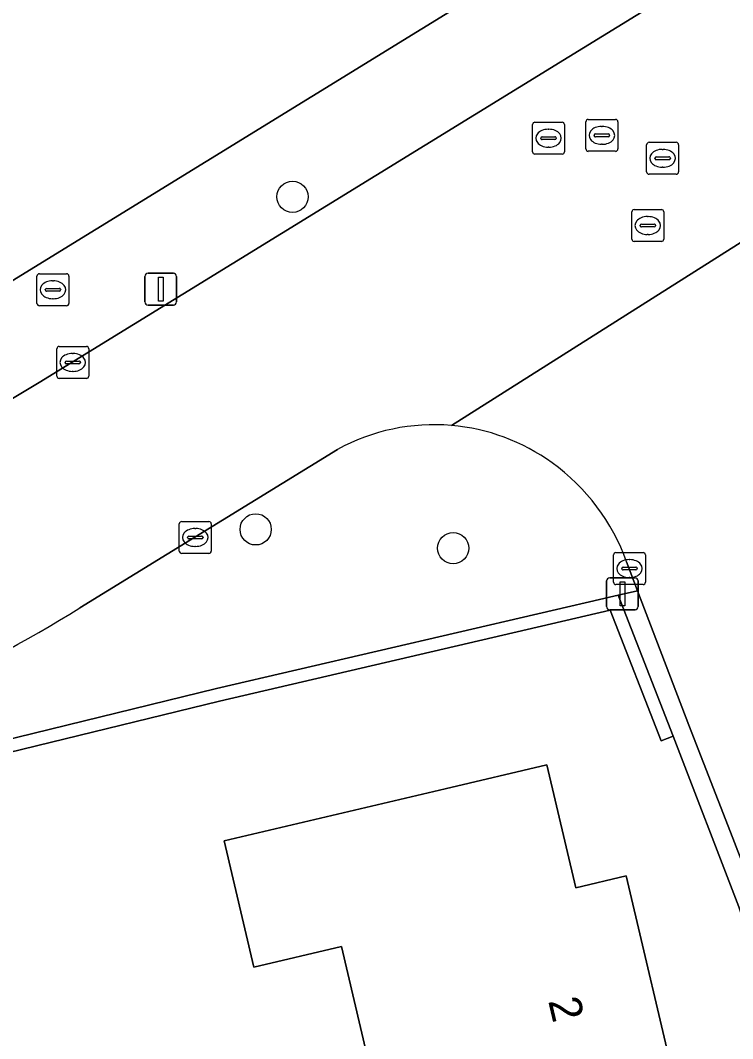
# Model space of a CAD drawing. Extents: x 157648 to 158502, y 379212 to 380938.
# Drawn here: x 158245.9 to 158268.23, y 380643.22 to 380675.11 of the extents above; entities that cross this region are included whole.
import ezdxf

# ---------------------------------------------------------------- set-up
doc = ezdxf.new("R2010")
doc.units = 0
for name, color, linetype in [('IMGEO_Boom', 7, 'Continuous'), ('IMGEO_Brandkraan', 7, 'Continuous'), ('IMGEO_Erf', 7, 'Continuous'), ('IMGEO_Groenvoorziening', 7, 'Continuous'), ('IMGEO_Haag', 7, 'Continuous'), ('IMGEO_Kolk', 7, 'Continuous'), ('IMGEO_Lichtmast', 7, 'Continuous'), ('IMGEO_Pand', 7, 'Continuous'), ('IMGEO_Pand_nummerreeks', 7, 'Continuous'), ('IMGEO_Rijbaan_lokaal_open', 7, 'Continuous'), ('IMGEO_Rioolput', 7, 'Continuous'), ('IMGEO_Voetpad_open', 7, 'Continuous')]:
    doc.layers.add(name, color=color, linetype=linetype)

msp = doc.modelspace()

# ---------------------------------------------------------------- linework, layer by layer
at = {"layer": 'IMGEO_Boom'}
for centre in [(158254.434, 380669.59), (158253.28, 380659.173), (158259.468, 380658.585)]:
    msp.add_circle(centre, 0.489, dxfattribs=at)
at = {"layer": 'IMGEO_Brandkraan'}
for p, q in [((158246.425, 380666.251), (158246.425, 380667.103)), ((158246.5, 380667.177), (158247.352, 380667.177)), ((158246.913, 380666.957), (158246.938, 380666.957)), ((158247.426, 380667.103), (158247.426, 380666.251)), ((158246.684, 380666.671), (158246.684, 380666.683)), ((158247.122, 380666.634), (158246.724, 380666.634)), ((158246.727, 380666.72), (158247.125, 380666.72)), ((158247.168, 380666.683), (158247.168, 380666.671)), ((158246.936, 380666.397), (158246.911, 380666.397)), ((158247.352, 380666.177), (158246.5, 380666.177))]:
    msp.add_line(p, q, dxfattribs=at)
for points in [[(158246.425, 380666.251), (158246.425, 380667.103)], [(158246.5, 380667.177), (158247.352, 380667.177)], [(158247.426, 380667.103), (158247.426, 380666.251)], [(158247.352, 380666.177), (158246.5, 380666.177)]]:
    msp.add_lwpolyline(points, dxfattribs=at)
for centre, radius, start, end in [((158246.502, 380667.101), 0.0765, 91.552, 178.448), ((158246.502, 380667.101), 0.0765, 91.552, 178.448), ((158247.35, 380667.101), 0.0765, 1.552, 88.448), ((158247.35, 380667.101), 0.0765, 1.552, 88.448), ((158246.724, 380666.68), 0.0403, 85.8775, 175.7526), ((158246.721, 380666.67), 0.0366, 178.938, 274.7102), ((158247.125, 380666.677), 0.043, 264.8664, 352.4533), ((158247.129, 380666.682), 0.0386, 1.7309, 96.639), ((158246.502, 380666.253), 0.0765, 181.552, 268.448), ((158246.502, 380666.253), 0.0765, 181.552, 268.448), ((158247.35, 380666.253), 0.0765, 271.552, 358.448), ((158247.35, 380666.253), 0.0765, 271.552, 358.448)]:
    msp.add_arc(centre, radius, start, end, dxfattribs=at)
for centre, major_axis, ratio, start_param, end_param in [((158246.912, 380666.677), (-0.387, 0.002), 0.722429, 4.712389, 7.853982), ((158246.937, 380666.677), (-0.39, 0.002), 0.717154, 1.570796, 4.712389)]:
    msp.add_ellipse(centre, major_axis=major_axis, ratio=ratio, start_param=start_param, end_param=end_param, dxfattribs=at)
at = {"layer": 'IMGEO_Erf'}
for points in [[(158244.961, 380666.536), (158268.56, 380681.046), (158278.546, 380687.175), (158281.278, 380688.781)], [(158270.472, 380641.386), (158268.423, 380647.352), (158266.359, 380652.693), (158265.986, 380652.548), (158264.393, 380656.642), (158252.147, 380653.798), (158240.661, 380650.992), (158240.566, 380651.381), (158230.925, 380649.086), (158227.242, 380648.21), (158204.018, 380642.406)], [(158257.561, 380639.351), (158255.967, 380646.114), (158253.226, 380645.468), (158252.295, 380649.421), (158259.217, 380651.052), (158262.407, 380651.804), (158263.315, 380647.952), (158264.89, 380648.323), (158266.508, 380641.458)]]:
    msp.add_lwpolyline(points, dxfattribs=at)
at = {"layer": 'IMGEO_Groenvoorziening'}
msp.add_lwpolyline([(158265.986, 380652.548), (158266.359, 380652.693), (158264.64, 380657.11), (158252.054, 380654.187), (158240.566, 380651.381), (158240.661, 380650.992), (158252.147, 380653.798), (158264.393, 380656.642)], close=True, dxfattribs=at)
at = {"layer": 'IMGEO_Haag'}
msp.add_lwpolyline([(158265.986, 380652.548), (158266.359, 380652.693), (158264.64, 380657.11), (158252.054, 380654.187), (158240.566, 380651.381), (158240.661, 380650.992), (158252.147, 380653.798), (158264.393, 380656.642)], close=True, dxfattribs=at)
at = {"layer": 'IMGEO_Kolk'}
for p, q in [((158247.046, 380663.975), (158247.046, 380664.827)), ((158247.121, 380664.901), (158247.973, 380664.901)), ((158247.534, 380664.681), (158247.559, 380664.681)), ((158248.047, 380664.827), (158248.047, 380663.975)), ((158247.305, 380664.395), (158247.305, 380664.407)), ((158247.743, 380664.358), (158247.345, 380664.358)), ((158247.348, 380664.444), (158247.746, 380664.444)), ((158247.789, 380664.407), (158247.789, 380664.395)), ((158247.557, 380664.121), (158247.532, 380664.121)), ((158247.973, 380663.901), (158247.121, 380663.901)), ((158250.886, 380658.494), (158250.886, 380659.346)), ((158250.961, 380659.42), (158251.813, 380659.42)), ((158251.887, 380659.346), (158251.887, 380658.494)), ((158251.145, 380658.914), (158251.145, 380658.926)), ((158251.188, 380658.963), (158251.586, 380658.963)), ((158251.374, 380659.2), (158251.399, 380659.2)), ((158251.629, 380658.926), (158251.629, 380658.914)), ((158251.583, 380658.877), (158251.185, 380658.877)), ((158251.397, 380658.64), (158251.372, 380658.64)), ((158251.813, 380658.42), (158250.961, 380658.42)), ((158264.493, 380657.52), (158264.493, 380658.372)), ((158264.568, 380658.446), (158265.42, 380658.446)), ((158265.494, 380658.372), (158265.494, 380657.52)), ((158264.752, 380657.94), (158264.752, 380657.952)), ((158264.795, 380657.989), (158265.193, 380657.989)), ((158264.981, 380658.226), (158265.006, 380658.226)), ((158265.236, 380657.952), (158265.236, 380657.94)), ((158265.19, 380657.903), (158264.792, 380657.903)), ((158265.004, 380657.666), (158264.979, 380657.666)), ((158265.42, 380657.446), (158264.568, 380657.446))]:
    msp.add_line(p, q, dxfattribs=at)
for points in [[(158247.046, 380663.975), (158247.046, 380664.827)], [(158247.121, 380664.901), (158247.973, 380664.901)], [(158248.047, 380664.827), (158248.047, 380663.975)], [(158247.973, 380663.901), (158247.121, 380663.901)], [(158250.886, 380658.494), (158250.886, 380659.346)], [(158250.961, 380659.42), (158251.813, 380659.42)], [(158251.887, 380659.346), (158251.887, 380658.494)], [(158251.813, 380658.42), (158250.961, 380658.42)], [(158264.493, 380657.52), (158264.493, 380658.372)], [(158264.568, 380658.446), (158265.42, 380658.446)], [(158265.494, 380658.372), (158265.494, 380657.52)], [(158265.42, 380657.446), (158264.568, 380657.446)]]:
    msp.add_lwpolyline(points, dxfattribs=at)
for centre, radius, start, end in [((158247.123, 380664.825), 0.0765, 91.552, 178.448), ((158247.123, 380664.825), 0.0765, 91.552, 178.448), ((158247.971, 380664.825), 0.0765, 1.552, 88.448), ((158247.971, 380664.825), 0.0765, 1.552, 88.448), ((158247.345, 380664.404), 0.0403, 85.8775, 175.7526), ((158247.342, 380664.394), 0.0366, 178.938, 274.7102), ((158247.746, 380664.401), 0.043, 264.8664, 352.4533), ((158247.75, 380664.406), 0.0386, 1.7309, 96.639), ((158247.123, 380663.977), 0.0765, 181.552, 268.448), ((158247.123, 380663.977), 0.0765, 181.552, 268.448), ((158247.971, 380663.977), 0.0765, 271.552, 358.448), ((158247.971, 380663.977), 0.0765, 271.552, 358.448), ((158250.963, 380659.344), 0.0765, 91.552, 178.448), ((158250.963, 380659.344), 0.0765, 91.552, 178.448), ((158251.811, 380659.344), 0.0765, 1.552, 88.448), ((158251.811, 380659.344), 0.0765, 1.552, 88.448), ((158251.185, 380658.923), 0.0403, 85.8775, 175.7526), ((158251.182, 380658.913), 0.0366, 178.938, 274.7102), ((158251.586, 380658.92), 0.043, 264.8664, 352.4533), ((158251.59, 380658.925), 0.0386, 1.7309, 96.639), ((158250.963, 380658.496), 0.0765, 181.552, 268.448), ((158250.963, 380658.496), 0.0765, 181.552, 268.448), ((158251.811, 380658.496), 0.0765, 271.552, 358.448), ((158251.811, 380658.496), 0.0765, 271.552, 358.448), ((158264.57, 380658.37), 0.0765, 91.552, 178.448), ((158264.57, 380658.37), 0.0765, 91.552, 178.448), ((158265.418, 380658.37), 0.0765, 1.552, 88.448), ((158265.418, 380658.37), 0.0765, 1.552, 88.448), ((158264.792, 380657.949), 0.0403, 85.8775, 175.7526), ((158265.197, 380657.951), 0.0386, 1.7309, 96.639), ((158264.789, 380657.939), 0.0366, 178.938, 274.7102), ((158265.193, 380657.946), 0.043, 264.8664, 352.4533), ((158264.57, 380657.522), 0.0765, 181.552, 268.448), ((158264.57, 380657.522), 0.0765, 181.552, 268.448), ((158265.418, 380657.522), 0.0765, 271.552, 358.448), ((158265.418, 380657.522), 0.0765, 271.552, 358.448)]:
    msp.add_arc(centre, radius, start, end, dxfattribs=at)
for centre, major_axis, ratio, start_param, end_param in [((158247.533, 380664.401), (-0.387, 0.002), 0.722429, 4.712389, 7.853982), ((158247.558, 380664.401), (-0.39, 0.002), 0.717154, 1.570796, 4.712389), ((158251.373, 380658.92), (-0.387, 0.002), 0.722429, 4.712389, 7.853982), ((158251.398, 380658.92), (-0.39, 0.002), 0.717154, 1.570796, 4.712389), ((158264.98, 380657.946), (-0.387, 0.002), 0.722429, 4.712389, 7.853982), ((158265.005, 380657.946), (-0.39, 0.002), 0.717154, 1.570796, 4.712389)]:
    msp.add_ellipse(centre, major_axis=major_axis, ratio=ratio, start_param=start_param, end_param=end_param, dxfattribs=at)
at = {"layer": 'IMGEO_Lichtmast'}
for p, q in [((158249.81, 380666.295), (158249.81, 380667.095)), ((158249.81, 380667.095), (158249.81, 380666.295)), ((158249.91, 380667.195), (158250.7, 380667.195)), ((158250.7, 380667.195), (158249.91, 380667.195)), ((158250.8, 380667.095), (158250.8, 380666.295)), ((158250.8, 380666.295), (158250.8, 380667.095)), ((158250.7, 380666.195), (158249.91, 380666.195)), ((158249.91, 380666.195), (158250.7, 380666.195)), ((158264.378, 380657.657), (158265.168, 380657.657)), ((158265.168, 380657.657), (158264.378, 380657.657)), ((158264.278, 380656.757), (158264.278, 380657.557)), ((158264.278, 380657.557), (158264.278, 380656.757)), ((158265.268, 380657.557), (158265.268, 380656.757)), ((158265.268, 380656.757), (158265.268, 380657.557)), ((158265.168, 380656.657), (158264.378, 380656.657)), ((158264.378, 380656.657), (158265.168, 380656.657))]:
    msp.add_line(p, q, dxfattribs=at)
for points in [[(158250.23, 380667.07), (158250.38, 380667.07), (158250.38, 380666.32), (158250.23, 380666.32), (158250.23, 380667.07)], [(158264.698, 380657.532), (158264.848, 380657.532), (158264.848, 380656.782), (158264.698, 380656.782), (158264.698, 380657.532)]]:
    msp.add_lwpolyline(points, dxfattribs=at)
for centre, start, end in [((158249.91, 380667.095), 90, 180), ((158249.91, 380667.095), 90, 180), ((158250.7, 380667.095), 0, 90), ((158250.7, 380667.095), 360, 90), ((158249.91, 380666.295), 180, 270), ((158249.91, 380666.295), 180, 270), ((158250.7, 380666.295), 270, 0), ((158250.7, 380666.295), 270, 0), ((158264.378, 380657.557), 90, 180), ((158264.378, 380657.557), 90, 180), ((158265.168, 380657.557), 0, 90), ((158265.168, 380657.557), 360, 90), ((158264.378, 380656.757), 180, 270), ((158264.378, 380656.757), 180, 270), ((158265.168, 380656.757), 270, 0), ((158265.168, 380656.757), 270, 0)]:
    msp.add_arc(centre, 0.1, start, end, dxfattribs=at)
at = {"layer": 'IMGEO_Pand'}
msp.add_lwpolyline([(158262.407, 380651.804), (158259.217, 380651.052), (158252.295, 380649.421), (158253.226, 380645.468), (158255.967, 380646.114), (158257.561, 380639.351), (158266.508, 380641.458), (158264.89, 380648.323), (158263.315, 380647.952)], close=True, dxfattribs=at)
at = {"layer": 'IMGEO_Rijbaan_lokaal_open'}
for points in [[(158280.194, 380684.478), (158268.424, 380677.249), (158268.233, 380677.131), (158263.098, 380673.967), (158246.494, 380663.768), (158243.889, 380662.222), (158239.92, 380659.948)], [(158269.209, 380668.62), (158259.413, 380662.428)], [(158259.413, 380662.428), (158269.209, 380668.62)], [(158247.773, 380656.714), (158255.847, 380661.679)], [(158264.905, 380658.157), (158265.25, 380657.252), (158266.856, 380653.04), (158268.233, 380649.501), (158268.951, 380647.635), (158271.067, 380641.515), (158273.069, 380635.27), (158274.89, 380628.688), (158275.399, 380626.75), (158277.479, 380617.972), (158278.213, 380614.328)]]:
    msp.add_lwpolyline(points, dxfattribs=at)
for centre, radius, start, end in [((158258.874, 380656.129), 6.322, 85.1134, 118.6105), ((158258.879, 380656.149), 6.302, 54.1519, 85.1345), ((158258.703, 380655.913), 6.596, 19.8874, 54.1122), ((158215.577, 380709.566), 61.886, 290.21525, 301.3483)]:
    msp.add_arc(centre, radius, start, end, dxfattribs=at)
at = {"layer": 'IMGEO_Rioolput'}
for p, q in [((158263.704, 380672.012), (158264.556, 380672.012)), ((158261.956, 380670.997), (158261.956, 380671.849)), ((158262.031, 380671.923), (158262.883, 380671.923)), ((158262.444, 380671.703), (158262.469, 380671.703)), ((158262.957, 380671.849), (158262.957, 380670.997)), ((158263.629, 380671.086), (158263.629, 380671.938)), ((158264.117, 380671.792), (158264.142, 380671.792)), ((158264.63, 380671.938), (158264.63, 380671.086)), ((158262.215, 380671.417), (158262.215, 380671.429)), ((158262.653, 380671.38), (158262.255, 380671.38)), ((158262.258, 380671.466), (158262.656, 380671.466)), ((158262.699, 380671.429), (158262.699, 380671.417)), ((158263.888, 380671.506), (158263.888, 380671.518)), ((158264.326, 380671.469), (158263.928, 380671.469)), ((158263.931, 380671.555), (158264.329, 380671.555)), ((158264.372, 380671.518), (158264.372, 380671.506)), ((158262.467, 380671.143), (158262.442, 380671.143)), ((158264.14, 380671.232), (158264.115, 380671.232)), ((158265.532, 380670.368), (158265.532, 380671.22)), ((158265.607, 380671.294), (158266.459, 380671.294)), ((158266.02, 380671.074), (158266.045, 380671.074)), ((158266.533, 380671.22), (158266.533, 380670.368)), ((158262.883, 380670.923), (158262.031, 380670.923)), ((158264.556, 380671.012), (158263.704, 380671.012)), ((158265.791, 380670.788), (158265.791, 380670.8)), ((158266.229, 380670.751), (158265.831, 380670.751)), ((158265.834, 380670.837), (158266.232, 380670.837)), ((158266.275, 380670.8), (158266.275, 380670.788)), ((158266.043, 380670.514), (158266.018, 380670.514)), ((158266.459, 380670.294), (158265.607, 380670.294)), ((158265.067, 380668.263), (158265.067, 380669.115)), ((158265.142, 380669.189), (158265.994, 380669.189)), ((158266.068, 380669.115), (158266.068, 380668.263)), ((158265.555, 380668.969), (158265.58, 380668.969)), ((158265.326, 380668.683), (158265.326, 380668.695)), ((158265.764, 380668.646), (158265.366, 380668.646)), ((158265.369, 380668.732), (158265.767, 380668.732)), ((158265.81, 380668.695), (158265.81, 380668.683)), ((158265.994, 380668.189), (158265.142, 380668.189)), ((158265.578, 380668.409), (158265.553, 380668.409))]:
    msp.add_line(p, q, dxfattribs=at)
for points in [[(158263.704, 380672.012), (158264.556, 380672.012)], [(158261.956, 380670.997), (158261.956, 380671.849)], [(158262.031, 380671.923), (158262.883, 380671.923)], [(158262.957, 380671.849), (158262.957, 380670.997)], [(158263.629, 380671.086), (158263.629, 380671.938)], [(158264.63, 380671.938), (158264.63, 380671.086)], [(158265.532, 380670.368), (158265.532, 380671.22)], [(158265.607, 380671.294), (158266.459, 380671.294)], [(158266.533, 380671.22), (158266.533, 380670.368)], [(158262.883, 380670.923), (158262.031, 380670.923)], [(158264.556, 380671.012), (158263.704, 380671.012)], [(158266.459, 380670.294), (158265.607, 380670.294)], [(158265.067, 380668.263), (158265.067, 380669.115)], [(158265.142, 380669.189), (158265.994, 380669.189)], [(158266.068, 380669.115), (158266.068, 380668.263)], [(158265.994, 380668.189), (158265.142, 380668.189)]]:
    msp.add_lwpolyline(points, dxfattribs=at)
for centre, radius, start, end in [((158263.706, 380671.936), 0.0765, 91.552, 178.448), ((158263.706, 380671.936), 0.0765, 91.552, 178.448), ((158264.554, 380671.936), 0.0765, 1.552, 88.448), ((158264.554, 380671.936), 0.0765, 1.552, 88.448), ((158262.033, 380671.847), 0.0765, 91.552, 178.448), ((158262.033, 380671.847), 0.0765, 91.552, 178.448), ((158262.881, 380671.847), 0.0765, 1.552, 88.448), ((158262.881, 380671.847), 0.0765, 1.552, 88.448), ((158262.255, 380671.426), 0.0403, 85.8775, 175.7526), ((158262.252, 380671.416), 0.0366, 178.938, 274.7102), ((158262.656, 380671.423), 0.043, 264.8664, 352.4533), ((158262.66, 380671.428), 0.0386, 1.7309, 96.639), ((158263.928, 380671.515), 0.0403, 85.8775, 175.7526), ((158263.925, 380671.505), 0.0366, 178.938, 274.7102), ((158264.329, 380671.512), 0.043, 264.8664, 352.4533), ((158264.333, 380671.517), 0.0386, 1.7309, 96.639), ((158263.706, 380671.088), 0.0765, 181.552, 268.448), ((158263.706, 380671.088), 0.0765, 181.552, 268.448), ((158264.554, 380671.088), 0.0765, 271.552, 358.448), ((158264.554, 380671.088), 0.0765, 271.552, 358.448), ((158265.609, 380671.218), 0.0765, 91.552, 178.448), ((158265.609, 380671.218), 0.0765, 91.552, 178.448), ((158266.457, 380671.218), 0.0765, 1.552, 88.448), ((158266.457, 380671.218), 0.0765, 1.552, 88.448), ((158262.033, 380670.999), 0.0765, 181.552, 268.448), ((158262.033, 380670.999), 0.0765, 181.552, 268.448), ((158262.881, 380670.999), 0.0765, 271.552, 358.448), ((158262.881, 380670.999), 0.0765, 271.552, 358.448), ((158265.831, 380670.797), 0.0403, 85.8775, 175.7526), ((158265.828, 380670.787), 0.0366, 178.938, 274.7102), ((158266.232, 380670.794), 0.043, 264.8664, 352.4533), ((158266.236, 380670.799), 0.0386, 1.7309, 96.639), ((158265.609, 380670.37), 0.0765, 181.552, 268.448), ((158265.609, 380670.37), 0.0765, 181.552, 268.448), ((158266.457, 380670.37), 0.0765, 271.552, 358.448), ((158266.457, 380670.37), 0.0765, 271.552, 358.448), ((158265.144, 380669.113), 0.0765, 91.552, 178.448), ((158265.144, 380669.113), 0.0765, 91.552, 178.448), ((158265.992, 380669.113), 0.0765, 1.552, 88.448), ((158265.992, 380669.113), 0.0765, 1.552, 88.448), ((158265.366, 380668.692), 0.0403, 85.8775, 175.7526), ((158265.363, 380668.682), 0.0366, 178.938, 274.7102), ((158265.767, 380668.689), 0.043, 264.8664, 352.4533), ((158265.771, 380668.694), 0.0386, 1.7309, 96.639), ((158265.144, 380668.265), 0.0765, 181.552, 268.448), ((158265.144, 380668.265), 0.0765, 181.552, 268.448), ((158265.992, 380668.265), 0.0765, 271.552, 358.448), ((158265.992, 380668.265), 0.0765, 271.552, 358.448)]:
    msp.add_arc(centre, radius, start, end, dxfattribs=at)
for centre, major_axis, ratio, start_param, end_param in [((158262.443, 380671.423), (-0.387, 0.002), 0.722429, 4.712389, 7.853982), ((158262.468, 380671.423), (-0.39, 0.002), 0.717154, 1.570796, 4.712389), ((158264.116, 380671.512), (-0.387, 0.002), 0.722429, 4.712389, 7.853982), ((158264.141, 380671.512), (-0.39, 0.002), 0.717154, 1.570796, 4.712389), ((158266.019, 380670.794), (-0.387, 0.002), 0.722429, 4.712389, 7.853982), ((158266.044, 380670.794), (-0.39, 0.002), 0.717154, 1.570796, 4.712389), ((158265.554, 380668.689), (-0.387, 0.002), 0.722429, 4.712389, 7.853982), ((158265.579, 380668.689), (-0.39, 0.002), 0.717154, 1.570796, 4.712389)]:
    msp.add_ellipse(centre, major_axis=major_axis, ratio=ratio, start_param=start_param, end_param=end_param, dxfattribs=at)
at = {"layer": 'IMGEO_Voetpad_open'}
for points in [[(158281.278, 380688.781), (158278.546, 380687.175), (158268.56, 380681.046), (158244.961, 380666.536), (158241.255, 380664.317)], [(158239.92, 380659.948), (158243.889, 380662.222), (158246.494, 380663.768), (158263.098, 380673.967), (158268.233, 380677.131), (158268.424, 380677.249), (158280.194, 380684.478)], [(158255.847, 380661.679), (158247.773, 380656.714)], [(158264.64, 380657.11), (158265.25, 380657.252), (158264.905, 380658.157)], [(158231.021, 380649.606), (158230.806, 380649.557), (158227.136, 380648.639), (158217.494, 380646.285), (158213.812, 380645.387), (158203.627, 380642.926), (158199.947, 380642.048), (158190.411, 380639.762), (158186.738, 380638.899), (158176.96, 380636.568), (158177.087, 380635.99), (158179.163, 380636.483), (158184.083, 380637.656), (158204.018, 380642.406), (158227.242, 380648.21), (158230.925, 380649.086), (158240.566, 380651.381), (158252.054, 380654.187), (158264.64, 380657.11)], [(158268.951, 380647.635), (158268.233, 380649.501), (158266.856, 380653.04), (158265.25, 380657.252), (158264.64, 380657.11), (158266.359, 380652.693), (158268.423, 380647.352), (158270.472, 380641.386), (158272.481, 380635.085), (158274.294, 380628.549), (158274.835, 380626.514), (158276.868, 380617.835), (158277.607, 380614.209)]]:
    msp.add_lwpolyline(points, dxfattribs=at)
for centre, radius, start, end in [((158258.874, 380656.129), 6.322, 85.1134, 118.6105), ((158258.879, 380656.149), 6.302, 54.1519, 85.1345), ((158258.703, 380655.913), 6.596, 19.8874, 54.1122), ((158215.577, 380709.566), 61.886, 290.21525, 301.3483)]:
    msp.add_arc(centre, radius, start, end, dxfattribs=at)

# ---------------------------------------------------------------- texts
at = {"layer": 'IMGEO_Pand_nummerreeks'}
msp.add_text('2', height=1, rotation=283.2638, dxfattribs=at).set_placement((158262.443, 380644.408))

doc.saveas('drawing.dxf')
